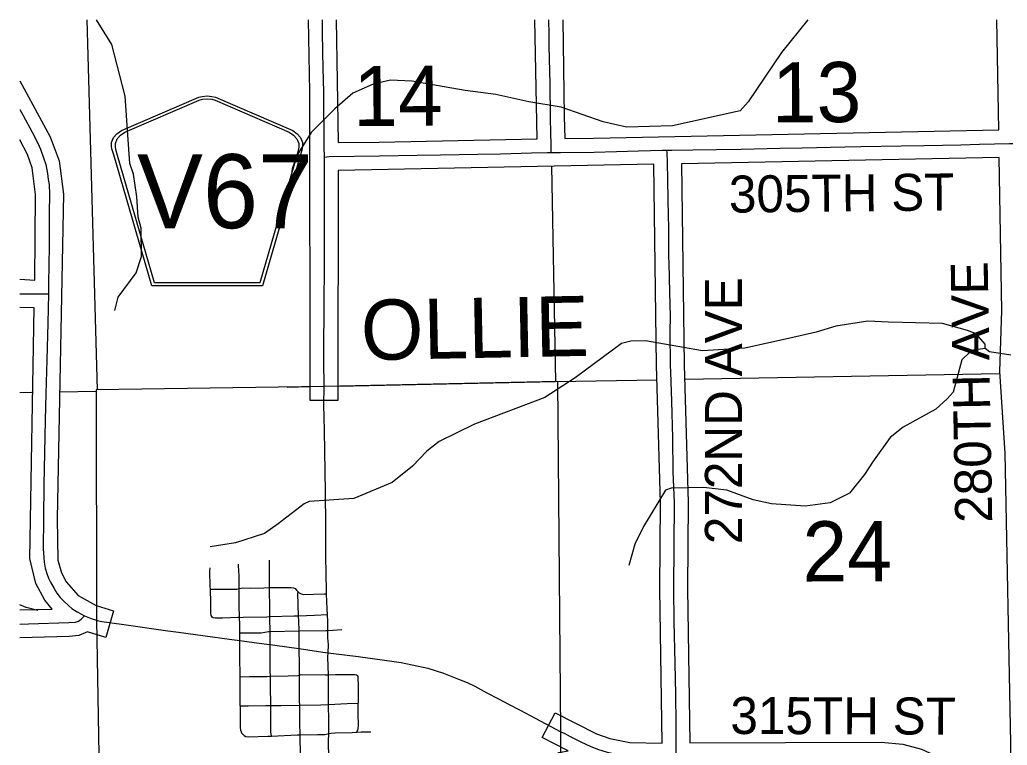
# Model space of a CAD drawing. Extents: x 10133 to 81668, y 7924 to 11018.
# Drawn here: x 10954.9 to 11275.1, y 9359.7 to 9594.9 of the extents above; entities that cross this region are included whole.
import ezdxf

# ---------------------------------------------------------------- set-up
doc = ezdxf.new("R2010")
doc.units = 0
for name, color, linetype in [('tdCoCityStreetMajor', 7, 'Continuous'), ('tdCoCityStreetMinor', 7, 'Continuous'), ('tdCoCoBndryTxt', 7, 'Continuous'), ('tdCoCorpBndry', 7, 'Continuous'), ('tdCoCorpPopTxt', 7, 'Continuous'), ('tdCoHydroRiver', 7, 'Continuous'), ('tdCoPriNonDiv', 7, 'Continuous'), ('tdCoRROwnerTxt', 7, 'Continuous'), ('tdCoSecRteBand', 7, 'Continuous'), ('tdCoShieldStRte', 7, 'Continuous'), ('tdCoStrucNonDivPri', 7, 'Continuous'), ('tdCoSurfConcUnbanded', 7, 'Continuous'), ('tdCoSurfEarth', 7, 'Continuous'), ('tdCoSurfGravel', 7, 'Continuous')]:
    doc.layers.add(name, color=color, linetype=linetype)

msp = doc.modelspace()

# ---------------------------------------------------------------- linework, layer by layer
at = {"layer": 'tdCoCityStreetMajor'}
msp.add_lwpolyline([(11167.68, 9355.9), (11167.68, 9356.85), (11167.73, 9366.66), (11167.65, 9376.13), (11167.41, 9386.27), (11167.11, 9399.66), (11166.94, 9410.44), (11167.14, 9438.38), (11166.74, 9448.29), (11166.62, 9459.39), (11166.32, 9471.28), (11165.98, 9480.62), (11165.83, 9482.89), (11165.78, 9493.67), (11165.88, 9498.77), (11165.63, 9506.44), (11165.46, 9516.13), (11165.34, 9517.98), (11165.32, 9522.55)], dxfattribs=at)
at = {"layer": 'tdCoCityStreetMinor'}
for points in [[(11127.18, 9551.84), (11127.23, 9554.92), (11127.1, 9557.81), (11126.93, 9563.48), (11126.83, 9574.13), (11126.58, 9586.34), (11126.49, 9590.19), (11126.46, 9594.78), (11126.46, 9594.91)], [(11164.7, 9552.62), (11166.32, 9552.66), (11173.1, 9552.73), (11180.83, 9552.85), (11188.82, 9552.97), (11201.49, 9553.27), (11208.55, 9553.39), (11222.38, 9553.66), (11227.56, 9553.78), (11240.68, 9554.03), (11248.18, 9554.18), (11260.04, 9554.4), (11266.08, 9554.52), (11275.82, 9554.8), (11276.91, 9554.82)], [(11053.65, 9550.33), (11055.26, 9550.53), (11071.51, 9550.75), (11083.74, 9551), (11091.26, 9551.15), (11103.44, 9551.37), (11110.74, 9551.47), (11120.78, 9551.71), (11125.91, 9551.81), (11127.18, 9551.84)], [(11127.18, 9551.84), (11130.17, 9551.91), (11141.12, 9552.01), (11148.42, 9552.23), (11155.5, 9552.43), (11163.29, 9552.58), (11164.7, 9552.62)], [(11165.32, 9522.55), (11165.31, 9527.97), (11165.21, 9530.98), (11165.01, 9542.84), (11164.94, 9548.78), (11164.79, 9551.72), (11164.7, 9552.62)], [(10954.88, 9506.03), (10960.82, 9506), (10963.02, 9506.08), (10964.17, 9506.08)], [(10954.88, 9398.93), (10957.69, 9399.05), (10970.79, 9399.44), (10973, 9399.59), (10973.94, 9399.89), (10974.83, 9400.58), (10975.86, 9401.68)], [(11130.34, 9364.07), (11131.03, 9363.71), (11131.37, 9363.54), (11133.32, 9362.55), (11136.8, 9360.82), (11140.1, 9359.22), (11142.54, 9358.33), (11144.99, 9357.57), (11147.31, 9356.98)]]:
    msp.add_lwpolyline(points, dxfattribs=at)
at = {"layer": 'tdCoCorpBndry'}
for points in [[(11054.08, 9430.94), (11053.98, 9441.86), (11053.88, 9448.56), (11053.76, 9454.9), (11053.69, 9461.81), (11053.51, 9470.07), (11053.54, 9475.87), (11053.54, 9475.95)], [(11054.86, 9389.67), (11056.6, 9389.43), (11064.57, 9388.39), (11076.31, 9386.77), (11078.57, 9386.45), (11083.6, 9385.44), (11087.21, 9384.65), (11092.33, 9382.99), (11097.14, 9381.14), (11100, 9379.96), (11102.4, 9378.78), (11106.34, 9376.66), (11110.14, 9374.68), (11113.37, 9372.96), (11117.09, 9371.01), (11122.03, 9368.47), (11130.34, 9364.07), (11130.34, 9364.07)]]:
    msp.add_lwpolyline(points, dxfattribs=at)
at = {"layer": 'tdCoCorpPopTxt'}
for points in [[(11016.68, 9410.33), (11016.66, 9411.14), (11016.53, 9416.08), (11016.58, 9417.21)], [(11026, 9410.45), (11026.05, 9413.49), (11025.99, 9414.5), (11025.78, 9417.91), (11025.78, 9418.35)], [(11035.84, 9410.8), (11035.88, 9416.52), (11035.86, 9419.65)], [(11016.68, 9410.33), (11018.85, 9410.33), (11025.29, 9410.33), (11026, 9410.45)], [(11026.14, 9401.1), (11025.61, 9401.06), (11020.65, 9400.91), (11018.28, 9400.89), (11017.64, 9400.98), (11017.3, 9401.21), (11017, 9401.75), (11016.83, 9402.56), (11016.83, 9405.84), (11016.68, 9410.33)], [(11026.14, 9401.1), (11026.03, 9405.04), (11025.98, 9409.2), (11026, 9410.45)], [(11026, 9410.45), (11027.29, 9410.68), (11029.68, 9410.65), (11034.04, 9410.73), (11035.84, 9410.8)], [(11035.99, 9401.38), (11036.01, 9402.96), (11035.93, 9405.28), (11035.86, 9409.03), (11035.83, 9409.62), (11035.84, 9410.8)], [(11035.84, 9410.8), (11037.15, 9410.85), (11041.44, 9410.87), (11042.92, 9410.87), (11043.59, 9410.75), (11044.18, 9410.5), (11044.62, 9409.96), (11045.17, 9409.43)], [(11045.29, 9401.62), (11045.09, 9408.85), (11045.17, 9409.43)], [(11045.17, 9409.43), (11045.53, 9409.07), (11046.08, 9408.78), (11046.92, 9408.56), (11053.65, 9408.78), (11054.35, 9408.8)], [(11026.14, 9401.1), (11027.33, 9401.21), (11034.98, 9401.35), (11035.99, 9401.38)], [(11026.24, 9396.1), (11026.2, 9398.8), (11026.14, 9401.1)], [(11036.07, 9396.55), (11035.98, 9400.76), (11035.99, 9401.38)], [(11035.99, 9401.38), (11043.88, 9401.58), (11045.29, 9401.62)], [(11045.29, 9401.62), (11050.42, 9401.8), (11054.64, 9402.04)], [(11045.46, 9396.74), (11045.34, 9400.02), (11045.29, 9401.62)], [(11026.34, 9381.89), (11026.25, 9388.56), (11026.23, 9392.63), (11026.23, 9393.65), (11026.25, 9395.71), (11026.24, 9396.1)], [(11026.24, 9396.1), (11028.84, 9396.12), (11033.13, 9396.17), (11035.52, 9396.54), (11036.07, 9396.55)], [(11036.15, 9382.02), (11036.13, 9383.92), (11036.03, 9391.39), (11036.07, 9392.32), (11036.13, 9393.79), (11036.07, 9396.55)], [(11036.07, 9396.55), (11045.46, 9396.74)], [(11045.46, 9396.74), (11054.14, 9396.91), (11054.79, 9396.92), (11056.38, 9396.94), (11059.34, 9397.18)], [(11045.61, 9382.43), (11045.61, 9384.61), (11045.61, 9386.85), (11045.53, 9389.94), (11045.53, 9390.99), (11045.53, 9392.85), (11045.51, 9395.31), (11045.46, 9396.74)], [(11026.34, 9381.89), (11029.38, 9381.99), (11034.97, 9381.99), (11036.15, 9382.02)], [(11026.37, 9372.5), (11026.4, 9377.47), (11026.34, 9381.89)], [(11036.15, 9382.02), (11041.87, 9382.19), (11045.02, 9382.29), (11045.61, 9382.43), (11045.61, 9382.43)], [(11036.28, 9372.54), (11036.3, 9373.46), (11036.22, 9378.06), (11036.15, 9381.63), (11036.15, 9382.02)], [(11045.61, 9382.43), (11046.18, 9382.56), (11054.06, 9382.52), (11054.94, 9382.53), (11057.3, 9382.58), (11063.58, 9382.66), (11063.97, 9382.54), (11064.04, 9382.52), (11064.17, 9382.43), (11064.39, 9382.27), (11064.45, 9381.91), (11064.57, 9378.59), (11064.62, 9374.28), (11064.63, 9373.29)], [(11045.65, 9372.69), (11045.61, 9373.86), (11045.61, 9382.43)], [(11026.37, 9372.5), (11026.35, 9369.5), (11026.35, 9365.43), (11026.45, 9364.57), (11026.67, 9364), (11026.92, 9363.51), (11027.04, 9363.38), (11027.19, 9363.21), (11027.63, 9362.79), (11028.15, 9362.5), (11028.99, 9362.35), (11035.3, 9362.59), (11036.48, 9362.64)], [(11026.37, 9372.5), (11028.94, 9372.43), (11034.66, 9372.53), (11036.28, 9372.54)], [(11036.48, 9362.64), (11036.33, 9364.04), (11036.25, 9371.42), (11036.28, 9372.54)], [(11036.28, 9372.54), (11039.61, 9372.57), (11045.65, 9372.69)], [(11045.65, 9372.69), (11052.49, 9372.82), (11055.01, 9372.92), (11061.07, 9373.17), (11064.63, 9373.29)], [(11045.79, 9363.05), (11045.78, 9363.8), (11045.66, 9366.16), (11045.68, 9371.74), (11045.65, 9372.69)], [(11064.22, 9363.92), (11064.65, 9364.99), (11064.67, 9366.24), (11064.64, 9369.71), (11064.63, 9373.29)], [(11036.48, 9362.64), (11044.87, 9363.03), (11045.79, 9363.05)], [(11045.79, 9363.05), (11051.55, 9363.16), (11053.75, 9363.2), (11055.06, 9363.47), (11055.79, 9363.62), (11057.1, 9363.7), (11062.62, 9363.8), (11064.22, 9363.92)], [(11055.1, 9350.75), (11050.91, 9350.52), (11049.6, 9350.45), (11048.29, 9350.42), (11046.97, 9350.51), (11046.49, 9350.88), (11046.08, 9351.69), (11046.03, 9353.17), (11045.93, 9356.97), (11045.81, 9362.12), (11045.79, 9363.05)], [(11064.22, 9363.92), (11065.58, 9364.03), (11068.76, 9363.98)]]:
    msp.add_lwpolyline(points, dxfattribs=at)
at = {"layer": 'tdCoHydroRiver'}
for points in [[(10985.68, 9500.66), (10986.79, 9504.94), (10992.58, 9512.86), (10994.39, 9518.09), (10994.23, 9527.33), (10993.23, 9530.86), (10992.88, 9537.49), (10991.81, 9544.81), (10990.57, 9548.34), (10989.94, 9557.57), (10989.02, 9570.1), (10984.71, 9586.84), (10979.72, 9594.91)], [(11210.41, 9594.91), (11201.89, 9584.33), (11191.03, 9568.28), (11188.47, 9565.39), (11166.53, 9560.53), (11151.62, 9560.04), (11144.02, 9561.81), (11130.44, 9566.55), (11119.99, 9568.27), (11109.3, 9570.7), (11099.33, 9571.95), (11081.99, 9574.97), (11075.12, 9575.33), (11069.46, 9574.05), (11062.88, 9571.1), (11057.04, 9566.03), (11049.36, 9558.33), (11044.75, 9550.91), (11043.16, 9546.62), (11042.55, 9540.92)], [(11267.91, 9488.35), (11267.88, 9489.77), (11264.99, 9493.04), (11262.13, 9494.17), (11254.04, 9496.4), (11236.51, 9496.82), (11229.87, 9497.18), (11219.48, 9495.59), (11213.12, 9493.59), (11204.16, 9491.54), (11190, 9488.46), (11176.28, 9487.52), (11157.76, 9490.76), (11153.02, 9490.68), (11149.96, 9489.92), (11134.99, 9478.78), (11125.15, 9472.46), (11102.33, 9463.78), (11090.82, 9458.15), (11086.85, 9455), (11082.19, 9450.19), (11075.65, 9444.87), (11063.19, 9439.69), (11048.76, 9438.73), (11047.11, 9437.99), (11038.7, 9431.46), (11034.25, 9428.31), (11024.83, 9425.31), (11016.57, 9423.99)], [(11267.91, 9488.35), (11264.13, 9487.81), (11262.96, 9487.08), (11260.39, 9484.67), (11257.49, 9474.2), (11255.63, 9472.04), (11251.9, 9468.66), (11241.34, 9462.8), (11237.14, 9459.42), (11231.35, 9451.5), (11228.81, 9447.44), (11223.94, 9441.44), (11217.6, 9438.25), (11209.57, 9437.17), (11198.66, 9437.93), (11192.72, 9439.25), (11184.14, 9442.43), (11176.55, 9443.24), (11166.14, 9443.07), (11164.25, 9442.33), (11157.11, 9430.61), (11154.36, 9424.88), (11152.35, 9417.97)], [(11276.23, 9486.12), (11269.35, 9487.19), (11267.91, 9488.35)], [(10960.79, 9403.4), (10956.99, 9404.28), (10954.88, 9405.17)]]:
    msp.add_lwpolyline(points, dxfattribs=at)
at = {"layer": 'tdCoPriNonDiv'}
msp.add_line((10954.88, 9510.77), (10959.74, 9510.51), dxfattribs=at)
for points in [[(11130.85, 9108.64), (11127.4, 9236.64), (11125.97, 9350.74), (11126.35, 9353.88), (11127.46, 9355.88), (11129.68, 9357.35), (11132.65, 9357.86), (11124.27, 9362.2), (11128.47, 9370.15), (11141.86, 9363.37), (11146.21, 9361.9), (11152.66, 9360.56), (11163.2, 9360.35), (11162.44, 9410.37), (11162.64, 9438.3), (11161.33, 9482.87), (11160.45, 9548.03), (11058.16, 9546.07), (11058.02, 9471.43), (11049.02, 9471.47), (11048.94, 9571.48), (11048.48, 9594.91)], [(11057.43, 9594.91), (11058.12, 9555.07), (11071.43, 9555.25)], [(11071.43, 9555.25), (11122.67, 9556.25), (11121.91, 9594.91)], [(11130.93, 9594.91), (11131.43, 9563.57), (11131.66, 9556.42), (11141.04, 9556.51)], [(11141.04, 9556.51), (11272.29, 9559.2), (11271.65, 9594.91)], [(10954.88, 9575.12), (10964.7, 9556.9), (10967.63, 9549.15), (10969.04, 9538.3), (10967.04, 9433.23), (10967.25, 9419.71), (10968.39, 9415.56), (10969.89, 9412.69), (10973.86, 9408.17), (10979.62, 9404.96), (10985.33, 9403.26), (10982.76, 9394.63), (10976.8, 9396.41), (10974.01, 9395.21), (10970.92, 9394.95), (10954.88, 9394.54)], [(10959.74, 9510.51), (10960.04, 9538.26), (10958.93, 9546.84), (10957.41, 9551.23), (10954.88, 9555.95)], [(11276.48, 9339.98), (11276.18, 9360.35), (11274.35, 9454.39), (11272.65, 9480.82), (11273.29, 9500.68), (11272.49, 9550.2), (11169.45, 9548.19), (11170.33, 9483.05), (11171.63, 9438.35), (11171.44, 9410.46), (11172.19, 9360.44), (11234.14, 9360.66), (11241.18, 9360.03), (11247.21, 9358.37), (11253.67, 9355.53), (11276.48, 9339.98)], [(10954.88, 9403.53), (10965.43, 9403.78), (10963.01, 9406.69), (10960.06, 9412.13), (10958.15, 9420.27), (10959.58, 9501.51), (10954.88, 9501.57)]]:
    msp.add_lwpolyline(points, dxfattribs=at)
at = {"layer": 'tdCoSecRteBand'}
for points in [[(11053.54, 9475.95), (11053.54, 9476.7), (11053.49, 9483.53), (11053.51, 9491.5), (11053.56, 9498.11), (11053.64, 9505.53), (11053.66, 9512.16), (11053.71, 9518.28), (11053.66, 9525.48), (11053.66, 9533.22), (11053.66, 9540.2), (11053.66, 9547.33), (11053.65, 9550.33), (11053.64, 9553.67), (11053.59, 9558.97), (11053.49, 9566.02), (11053.44, 9571.55), (11053.29, 9579.24), (11053.19, 9584.44), (11053.05, 9590.98), (11053.01, 9594.91)], [(10954.88, 9565.8), (10955.99, 9563.81), (10958.87, 9558.43), (10960.7, 9554.85), (10961.58, 9552.91), (10962.57, 9550.09), (10963.29, 9548), (10963.85, 9545.04), (10964.1, 9543.16), (10964.37, 9541.49), (10964.54, 9538.36), (10964.47, 9532.17), (10964.37, 9521.54), (10964.22, 9509.35), (10964.17, 9506.25), (10964.17, 9506.08), (10963.98, 9496.51), (10963.63, 9484.6), (10963.29, 9473.57), (10963.14, 9465.06), (10962.94, 9454.46), (10962.72, 9444.25), (10962.55, 9433.28), (10962.5, 9423.36), (10962.64, 9420.5), (10962.79, 9419.07), (10963.16, 9417.05), (10963.68, 9415.37), (10964.22, 9413.84), (10964.84, 9412.54), (10966, 9410.44), (10966.86, 9409.01), (10967.97, 9407.58), (10969.23, 9406.37), (10970.83, 9404.84), (10971.77, 9404.03), (10973.47, 9402.94), (10975.86, 9401.68), (10978.08, 9400.72), (10979.73, 9400.23)]]:
    msp.add_lwpolyline(points, dxfattribs=at)
at = {"layer": 'tdCoStrucNonDivPri'}
for p, q in [((10976.59, 9594.91), (10979.95, 9474.93)), ((10954.88, 9474.09), (10958.81, 9474.15))]:
    msp.add_line(p, q, dxfattribs=at)
for points in [[(11127.33, 9547.4), (11128.6, 9477.61)], [(11058.07, 9476.13), (11128.6, 9477.61)], [(11128.6, 9477.61), (11161.53, 9478.2)], [(11128.6, 9477.61), (11128.6, 9477.57)], [(11170.53, 9478.36), (11272.68, 9480.19)], [(10967.82, 9474.29), (10979.7, 9474.49)], [(11041.58, 9475.78), (11049.08, 9475.94)]]:
    msp.add_lwpolyline(points, dxfattribs=at)
at = {"layer": 'tdCoSurfConcUnbanded'}
for points in [[(10997.66, 9508.68), (10985.37, 9551.11), (10984.78, 9553.08), (10984.68, 9553.97), (10984.68, 9555.14), (10985.31, 9556.69), (10986.4, 9557.96), (10987.84, 9558.96), (11012.93, 9569.81), (11014.06, 9570.06), (11015.62, 9570.19), (11017.19, 9570.06), (11018.31, 9569.81), (11043.4, 9558.96), (11044.84, 9557.96), (11045.93, 9556.69), (11046.57, 9555.14), (11046.57, 9553.97), (11046.46, 9553.08), (11045.88, 9551.11), (11033.59, 9508.68)], [(10998.54, 9509.63), (10986.58, 9550.92), (10986.02, 9552.81), (10985.91, 9553.66), (10985.91, 9554.78), (10986.52, 9556.27), (10987.57, 9557.49), (10988.95, 9558.45), (11013.04, 9568.87), (11014.12, 9569.11), (11015.62, 9569.24), (11017.12, 9569.11), (11018.21, 9568.87), (11042.29, 9558.45), (11043.67, 9557.49), (11044.72, 9556.27), (11045.33, 9554.78), (11045.33, 9553.66), (11045.23, 9552.81), (11044.67, 9550.92), (11032.71, 9509.63)]]:
    msp.add_lwpolyline(points, close=True, dxfattribs=at)
at = {"layer": 'tdCoSurfEarth'}
for points in [[(11054.86, 9389.67), (11054.94, 9392.29), (11054.82, 9394.46), (11054.79, 9396.92), (11054.75, 9399.66), (11054.64, 9402.04), (11054.55, 9403.95), (11054.35, 9408.64), (11054.35, 9408.8), (11054.3, 9409.87), (11054.2, 9415.35), (11054.18, 9420.94), (11054.11, 9427.6), (11054.08, 9430.94)], [(10979.73, 9400.23), (10979.99, 9400.16), (10981.51, 9399.76), (10987.9, 9398.92), (11002.94, 9396.8), (11006.39, 9396.38), (11017.34, 9394.86), (11023.61, 9393.99), (11026.23, 9393.65), (11029.28, 9393.25), (11035.05, 9392.46), (11036.07, 9392.32), (11043.01, 9391.35), (11045.53, 9390.99), (11053.15, 9389.9), (11054.86, 9389.67)], [(11055.31, 9327.59), (11055.31, 9328.98), (11055.24, 9333.79), (11055.14, 9340.77), (11055.14, 9347.26), (11055.1, 9350.75), (11055.07, 9354.24), (11055.09, 9355.47), (11055.04, 9360.94), (11055.06, 9363.47), (11055.07, 9365.28), (11055.07, 9367.7), (11055.01, 9372.92), (11054.99, 9374.53), (11054.94, 9381.44), (11054.94, 9382.53), (11054.92, 9385.23), (11054.82, 9388.34), (11054.86, 9389.67), (11054.86, 9389.67)]]:
    msp.add_lwpolyline(points, dxfattribs=at)
at = {"layer": 'tdCoSurfGravel'}
msp.add_lwpolyline([(11129.32, 9477.58), (11053.54, 9475.95), (10979.69, 9474.92), (10979.73, 9400.23), (10981.1, 9325.46), (10985.57, 9325.54), (10993.61, 9325.69), (11009.05, 9326.13), (11015.56, 9326.25), (11027.08, 9326.48), (11039.73, 9326.9), (11043.65, 9327.04), (11051.37, 9327.44), (11055.31, 9327.59), (11130.52, 9328.92), (11130.44, 9334.01), (11130.42, 9339.47), (11130.44, 9345.59), (11130.46, 9350.72), (11130.34, 9364.07)], close=True, dxfattribs=at)

# ---------------------------------------------------------------- texts
at = {"layer": 'tdCoCoBndryTxt'}
msp.add_text('OLLIE', height=19.5, rotation=1.115, dxfattribs=at).set_placement((11065.67, 9484.51))
at = {"layer": 'tdCoRROwnerTxt'}
for s, rotation, p in [('14', 0.2256, (11063.05, 9560.43)), ('13', 0.2265, (11198.78, 9561.62)), ('24', 0.2266, (11208.7, 9412.75))]:
    msp.add_text(s, height=19.5, rotation=rotation, dxfattribs=at).set_placement(p)
at = {"layer": 'tdCoShieldStRte'}
for s, rotation, p in [('305TH ST', 0.5977, (11184.87, 9532.34)), ('280TH AVE', 91, (11270.2, 9431.89)), ('272ND AVE', 90, (11189.04, 9424.87)), ('315TH ST', 359.8344, (11185.28, 9363.32))]:
    msp.add_text(s, height=12, rotation=rotation, dxfattribs=at).set_placement(p)
at = {"layer": 'tdCoSurfConcUnbanded'}
msp.add_text('V67', height=24, dxfattribs=at).set_placement((10992.89, 9527.32))

doc.saveas('drawing.dxf')
